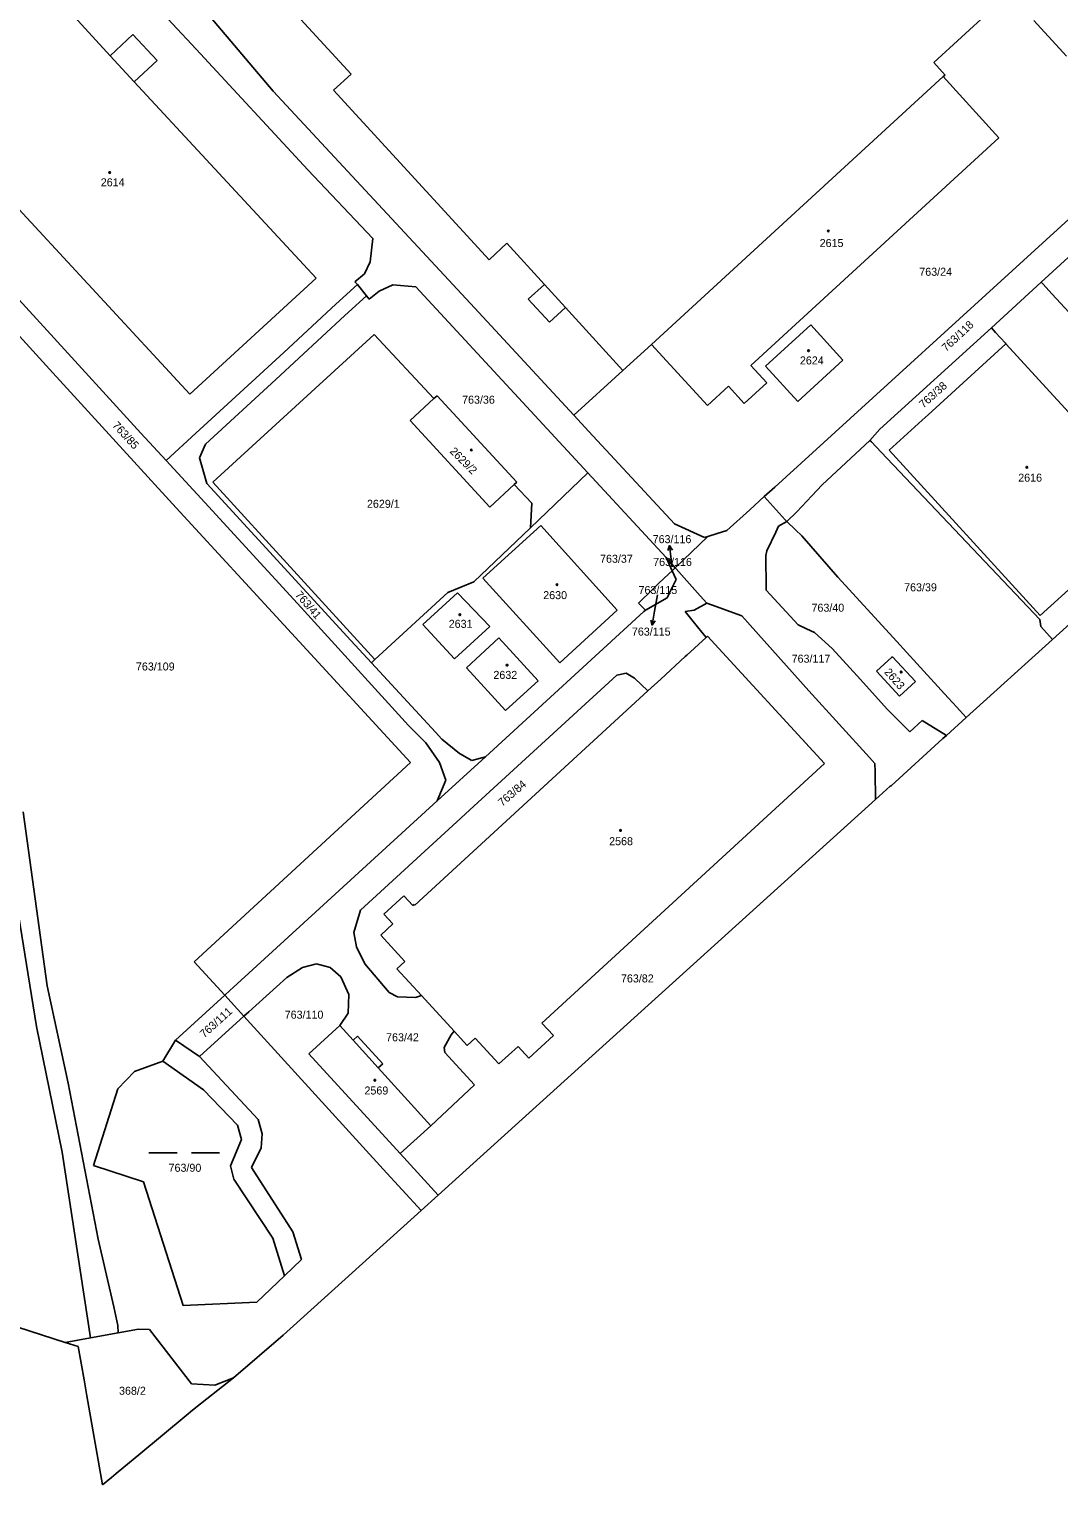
# Model space of a CAD drawing. Extents: x -735249 to -729401, y -1124843 to -1121828.
# Drawn here: x -733685.5 to -733466.8, y -1124842.6 to -1124533.4 of the extents above; entities that cross this region are included whole.
import ezdxf

# ---------------------------------------------------------------- set-up
doc = ezdxf.new("R2010")
doc.units = 0
for name, color, linetype in [('Vrstva 1', 7, 'Continuous'), ('Vrstva 13', 7, 'Continuous'), ('Vrstva 16', 7, 'Continuous'), ('Vrstva 18', 7, 'Continuous'), ('Vrstva 19', 7, 'Continuous'), ('Vrstva 25', 7, 'Continuous'), ('Vrstva 4', 7, 'Continuous')]:
    doc.layers.add(name, color=color, linetype=linetype)

msp = doc.modelspace()

# ---------------------------------------------------------------- linework, layer by layer
at = {"layer": 'Vrstva 1'}
for points in [[(-733684.28, -1124521.51), (-733668.29, -1124539.07)], [(-733617.15, -1124542.95), (-733636.87, -1124521.46)], [(-733660.09, -1124526.84), (-733650.07, -1124537.7)], [(-733633.7, -1124546.56), (-733647.02, -1124530.84)], [(-733481.62, -1124529.75), (-733493.36, -1124540.48)], [(-733472.16, -1124531.61), (-733465.23, -1124539.12)], [(-733668.29, -1124539.07), (-733663.46, -1124534.57)], [(-733663.46, -1124534.57), (-733658.34, -1124540.06)], [(-733658.34, -1124540.06), (-733663.18, -1124544.58)], [(-733650.07, -1124537.7), (-733626.34, -1124563.31)], [(-733493.36, -1124540.48), (-733490.98, -1124543.16)], [(-733617.15, -1124542.95), (-733620.86, -1124546.35)], [(-733491.39, -1124543.5), (-733553.34, -1124600.36)], [(-733490.98, -1124543.16), (-733491.39, -1124543.5)], [(-733479.6, -1124556.51), (-733491.39, -1124543.5)], [(-733651.42, -1124610.95), (-733711.16, -1124546.38)], [(-733624.55, -1124586.31), (-733663.18, -1124544.58)], [(-733591.78, -1124591.68), (-733633.7, -1124546.56)], [(-733620.86, -1124546.35), (-733587.79, -1124582.38)], [(-733532.23, -1124604.87), (-733479.6, -1124556.51)], [(-733470.57, -1124587.16), (-733459.91, -1124577.41), (-733457.7, -1124575.39), (-733442.33, -1124561.34)], [(-733626.34, -1124563.31), (-733612.53, -1124577.84)], [(-733458.57, -1124568.11), (-733461.75, -1124571.01), (-733463.97, -1124573.03), (-733527.19, -1124630.66)], [(-733655.04, -1124634.25), (-733680.48, -1124606.38), (-733705.37, -1124579.11)], [(-733613.09, -1124582.85), (-733612.53, -1124577.84)], [(-733587.79, -1124582.38), (-733584.09, -1124578.9)], [(-733584.09, -1124578.9), (-733576.09, -1124587.66)], [(-733694.59, -1124583.39), (-733681.69, -1124597.39)], [(-733614.28, -1124585.35), (-733613.09, -1124582.85)], [(-733651.42, -1124610.95), (-733624.55, -1124586.31)], [(-733616.33, -1124587.05), (-733614.28, -1124585.35)], [(-733616.33, -1124587.05), (-733615.8, -1124587.67)], [(-733615.8, -1124587.67), (-733620.35, -1124591.82)], [(-733618.45, -1124594.2), (-733613.89, -1124590.03)], [(-733615.8, -1124587.67), (-733613.89, -1124590.03)], [(-733613.89, -1124590.03), (-733613.27, -1124590.77)], [(-733611.21, -1124589.07), (-733613.27, -1124590.77)], [(-733608.28, -1124587.75), (-733611.21, -1124589.07)], [(-733603.37, -1124588.13), (-733608.28, -1124587.75)], [(-733580.75, -1124612.6), (-733603.37, -1124588.13)], [(-733576.09, -1124587.66), (-733579.51, -1124590.79)], [(-733481.14, -1124596.86), (-733470.57, -1124587.16)], [(-733470.57, -1124587.16), (-733470.26, -1124587.49), (-733468.23, -1124589.7), (-733457.62, -1124601.18)], [(-733631.44, -1124602.08), (-733620.35, -1124591.82)], [(-733591.78, -1124591.68), (-733569.83, -1124615.39)], [(-733579.51, -1124590.79), (-733575.02, -1124595.64)], [(-733575.02, -1124595.64), (-733571.63, -1124592.54)], [(-733571.63, -1124592.54), (-733559.42, -1124605.9)], [(-733618.45, -1124594.2), (-733633.14, -1124607.81)], [(-733519.53, -1124596.24), (-733529.12, -1124605.02)], [(-733512.71, -1124603.69), (-733519.53, -1124596.24)], [(-733681.69, -1124597.39), (-733661.76, -1124619.22)], [(-733646.49, -1124629.63), (-733612.26, -1124598.24)], [(-733612.26, -1124598.24), (-733599.54, -1124611.87)], [(-733504.86, -1124618.4), (-733481.14, -1124596.86)], [(-733481.14, -1124596.86), (-733480.26, -1124597.83), (-733478.17, -1124600.11), (-733478.07, -1124600.22)], [(-733650.09, -1124619.2), (-733631.44, -1124602.08)], [(-733559.42, -1124605.9), (-733553.34, -1124600.36)], [(-733553.34, -1124600.36), (-733541.48, -1124613.33)], [(-733478.07, -1124600.22), (-733486.33, -1124607.75)], [(-733478.07, -1124600.22), (-733445.95, -1124635.32)], [(-733528.87, -1124608.55), (-733532.23, -1124604.87)], [(-733529.12, -1124605.02), (-733522.3, -1124612.47)], [(-733522.3, -1124612.47), (-733512.71, -1124603.69)], [(-733633.14, -1124607.81), (-733648.04, -1124621.55)], [(-733569.83, -1124615.39), (-733559.42, -1124605.9)], [(-733533.66, -1124612.93), (-733528.87, -1124608.55)], [(-733486.33, -1124607.75), (-733494.62, -1124615.32)], [(-733598.89, -1124611.28), (-733599.54, -1124611.87)], [(-733581.96, -1124629.61), (-733598.89, -1124611.28)], [(-733541.48, -1124613.33), (-733537.02, -1124609.25)], [(-733537.02, -1124609.25), (-733533.66, -1124612.93)], [(-733599.54, -1124611.87), (-733604.62, -1124616.5)], [(-733566.85, -1124627.66), (-733580.75, -1124612.6)], [(-733604.62, -1124616.5), (-733587.71, -1124634.95)], [(-733569.83, -1124615.39), (-733566.63, -1124618.88)], [(-733494.62, -1124615.32), (-733495.85, -1124616.44), (-733502.89, -1124622.85)], [(-733661.76, -1124619.22), (-733656.39, -1124624.99)], [(-733656.39, -1124624.99), (-733650.09, -1124619.2)], [(-733566.63, -1124618.88), (-733548.48, -1124638.45)], [(-733517.08, -1124630.19), (-733506.95, -1124620.75)], [(-733506.95, -1124620.75), (-733504.86, -1124618.4)], [(-733506.95, -1124620.75), (-733506.63, -1124621.09), (-733504.57, -1124623.26), (-733470.9, -1124658.76)], [(-733648.04, -1124621.55), (-733649.32, -1124624.45)], [(-733502.89, -1124622.85), (-733470.79, -1124657.97)], [(-733656.39, -1124624.99), (-733648.21, -1124633.91)], [(-733649.32, -1124624.45), (-733647.78, -1124629.92)], [(-733647.78, -1124629.92), (-733617.2, -1124663.24)], [(-733646.49, -1124629.63), (-733612.08, -1124667.31)], [(-733587.71, -1124634.95), (-733582.51, -1124630.12)], [(-733582.51, -1124630.12), (-733581.96, -1124629.61)], [(-733582.51, -1124630.12), (-733578.78, -1124634.11)], [(-733579.04, -1124639.3), (-733566.85, -1124627.66)], [(-733566.85, -1124627.66), (-733550.26, -1124645.62)], [(-733524.61, -1124638), (-733522.46, -1124635.9), (-733519.3, -1124632.54), (-733517.08, -1124630.19)], [(-733537.35, -1124639.92), (-733532.47, -1124635.47), (-733529.41, -1124632.68)], [(-733529.41, -1124632.68), (-733527.19, -1124630.66)], [(-733529.41, -1124632.68), (-733524.93, -1124637.64), (-733524.61, -1124638)], [(-733655.04, -1124634.25), (-733604.5, -1124689.14)], [(-733627.73, -1124656.24), (-733648.21, -1124633.91)], [(-733578.78, -1124634.11), (-733579.04, -1124639.3)], [(-733591.09, -1124650.8), (-733579.04, -1124639.3)], [(-733589.14, -1124649.99), (-733576.87, -1124638.86)], [(-733576.87, -1124638.86), (-733560.62, -1124656.78)], [(-733548.48, -1124638.45), (-733542.06, -1124641.4)], [(-733526.36, -1124638.94), (-733526.95, -1124640.21), (-733528.82, -1124644.19)], [(-733524.61, -1124638), (-733526.36, -1124638.94)], [(-733521.4, -1124641.03), (-733522.78, -1124639.73), (-733524.61, -1124638)], [(-733541.4, -1124641.19), (-733548.31, -1124647.8)], [(-733542.06, -1124641.4), (-733541.4, -1124641.19)], [(-733541.4, -1124641.19), (-733539.37, -1124640.56), (-733537.35, -1124639.92)], [(-733513.8, -1124649.78), (-733521.4, -1124641.03)], [(-733550.26, -1124645.62), (-733548.97, -1124648.43)], [(-733548.31, -1124647.8), (-733550.26, -1124645.62)], [(-733528.82, -1124644.19), (-733529.08, -1124645.21)], [(-733529.08, -1124645.21), (-733529.08, -1124645.38), (-733529.03, -1124651.93), (-733529.02, -1124652.59)], [(-733548.97, -1124648.43), (-733549.66, -1124649.09), (-733551.83, -1124651.17), (-733552.05, -1124651.38)], [(-733548.31, -1124647.8), (-733548.74, -1124648.22), (-733548.97, -1124648.43)], [(-733548.97, -1124648.43), (-733548.1, -1124650.31)], [(-733541.57, -1124655.32), (-733542.98, -1124653.75), (-733548.13, -1124648), (-733548.31, -1124647.8)], [(-733596.58, -1124653.09), (-733591.09, -1124650.8)], [(-733572.79, -1124667.98), (-733589.14, -1124649.99)], [(-733548.1, -1124650.31), (-733549.57, -1124653.28), (-733549.83, -1124653.8), (-733550.04, -1124654.22), (-733554.64, -1124656.84)], [(-733552.05, -1124651.38), (-733553.04, -1124652.33)], [(-733501.26, -1124663.49), (-733513.8, -1124649.78)], [(-733462.52, -1124650.43), (-733470.79, -1124657.97)], [(-733612.08, -1124667.31), (-733596.58, -1124653.09)], [(-733601.9, -1124659.84), (-733594.55, -1124653.1)], [(-733594.55, -1124653.1), (-733587.7, -1124660.25)], [(-733553.04, -1124652.33), (-733556.13, -1124655.29)], [(-733522.17, -1124659.9), (-733529.02, -1124652.59)], [(-733604.97, -1124681.29), (-733627.73, -1124656.24)], [(-733588.62, -1124687.94), (-733554.94, -1124657.11)], [(-733560.62, -1124656.78), (-733572.79, -1124667.98)], [(-733556.13, -1124655.29), (-733554.64, -1124656.84)], [(-733554.94, -1124657.11), (-733554.64, -1124656.84)], [(-733544.26, -1124656.79), (-733546.17, -1124657.11)], [(-733546.17, -1124657.11), (-733544.47, -1124659.24), (-733541.77, -1124662.61)], [(-733541.57, -1124655.32), (-733544.26, -1124656.79)], [(-733534.18, -1124658), (-733540.62, -1124655.66), (-733541.57, -1124655.32)], [(-733519.93, -1124673.91), (-733534.18, -1124658)], [(-733595.21, -1124667.15), (-733601.9, -1124659.84)], [(-733587.7, -1124660.25), (-733595.21, -1124667.15)], [(-733518.75, -1124661.55), (-733520.4, -1124660.75), (-733522.17, -1124659.9)], [(-733470.9, -1124658.76), (-733470.64, -1124660.27)], [(-733470.64, -1124660.27), (-733468.2, -1124663.04)], [(-733617.2, -1124663.24), (-733612.83, -1124668)], [(-733592.65, -1124669.04), (-733585.79, -1124662.69)], [(-733585.79, -1124662.69), (-733577.43, -1124671.79)], [(-733546.18, -1124666.67), (-733545.86, -1124666.37), (-733541.77, -1124662.61)], [(-733541.44, -1124662.31), (-733541.77, -1124662.61)], [(-733516.59, -1124689.4), (-733541.44, -1124662.31)], [(-733514.98, -1124664.92), (-733518.75, -1124661.55)], [(-733490.34, -1124675.42), (-733499.23, -1124665.7), (-733501.26, -1124663.49)], [(-733612.83, -1124668), (-733612.08, -1124667.31)], [(-733546.18, -1124666.67), (-733551.39, -1124671.45)], [(-733508.97, -1124671.56), (-733514.98, -1124664.92)], [(-733502.2, -1124666.75), (-733502.28, -1124666.82), (-733505.56, -1124669.75)], [(-733497.31, -1124671.99), (-733502.2, -1124666.75)], [(-733612.83, -1124668), (-733599.2, -1124682.74)], [(-733584.33, -1124678.12), (-733592.65, -1124669.04)], [(-733558.74, -1124670.18), (-733560.38, -1124670.54), (-733560.71, -1124670.61)], [(-733556.99, -1124671.26), (-733558.74, -1124670.18)], [(-733505.56, -1124669.75), (-733500.69, -1124675.08)], [(-733560.71, -1124670.61), (-733591.09, -1124698.46), (-733594.72, -1124701.79), (-733615.12, -1124720.49)], [(-733577.43, -1124671.79), (-733584.33, -1124678.12)], [(-733554.13, -1124673.97), (-733556.9, -1124671.34), (-733556.99, -1124671.26)], [(-733551.39, -1124671.45), (-733554.13, -1124673.97)], [(-733503.31, -1124677.82), (-733508.97, -1124671.56)], [(-733500.69, -1124675.08), (-733497.31, -1124671.99)], [(-733603.64, -1124719.45), (-733554.13, -1124673.97)], [(-733505.9, -1124689.4), (-733507.06, -1124688.12), (-733519.93, -1124673.91)], [(-733486.52, -1124679.6), (-733487.19, -1124678.87), (-733487.92, -1124678.07), (-733488.54, -1124677.39), (-733490.34, -1124675.42)], [(-733503.31, -1124677.82), (-733499.67, -1124681.46), (-733498.49, -1124682.63)], [(-733604.97, -1124681.29), (-733601.28, -1124685.02)], [(-733597.89, -1124684.24), (-733599.2, -1124682.74)], [(-733495.87, -1124680.23), (-733498.49, -1124682.63)], [(-733490.73, -1124683.41), (-733495.87, -1124680.23)], [(-733601.28, -1124685.02), (-733598.38, -1124689.14)], [(-733594.09, -1124687.25), (-733597.89, -1124684.24)], [(-733598.83, -1124697.31), (-733588.62, -1124687.94)], [(-733591.53, -1124688.73), (-733594.09, -1124687.25)], [(-733588.62, -1124687.94), (-733591.53, -1124688.73)], [(-733604.5, -1124689.14), (-733650.45, -1124731.5)], [(-733598.38, -1124689.14), (-733597.03, -1124692.92)], [(-733576.61, -1124744.51), (-733516.59, -1124689.4)], [(-733505.9, -1124689.4), (-733505.88, -1124691.08), (-733505.81, -1124697.05)], [(-733597.03, -1124692.92), (-733598.83, -1124697.31)], [(-733643.98, -1124738.6), (-733642.88, -1124737.59), (-733641.34, -1124736.19), (-733598.83, -1124697.31)], [(-733681.65, -1124736.59), (-733686.75, -1124699.66)], [(-733689.21, -1124712.77), (-733683.92, -1124745.21)], [(-733610.19, -1124721.39), (-733605.95, -1124717.45)], [(-733605.95, -1124717.45), (-733604.03, -1124719.54)], [(-733604.03, -1124719.54), (-733603.78, -1124719.3)], [(-733603.78, -1124719.3), (-733603.64, -1124719.45)], [(-733615.12, -1124720.49), (-733616.54, -1124725.29)], [(-733608.3, -1124723.45), (-733610.19, -1124721.39)], [(-733616.54, -1124725.29), (-733616.02, -1124728.29)], [(-733610.85, -1124725.8), (-733608.3, -1124723.45)], [(-733605.71, -1124731.41), (-733610.85, -1124725.8)], [(-733616.02, -1124728.29), (-733614.24, -1124731.92)], [(-733650.45, -1124731.5), (-733643.98, -1124738.6)], [(-733627.45, -1124732.67), (-733624.5, -1124731.89)], [(-733624.5, -1124731.89), (-733621.59, -1124732.72)], [(-733614.24, -1124731.92), (-733609.06, -1124738.01)], [(-733607.41, -1124732.96), (-733605.71, -1124731.41)], [(-733639.91, -1124743.06), (-733638.85, -1124742.1), (-733637.38, -1124740.75), (-733630.82, -1124734.79)], [(-733630.82, -1124734.79), (-733627.45, -1124732.67)], [(-733621.59, -1124732.72), (-733619.34, -1124734.7)], [(-733619.34, -1124734.7), (-733617.62, -1124738.42)], [(-733602.2, -1124738.65), (-733607.41, -1124732.96)], [(-733681.65, -1124736.59), (-733677.19, -1124757.27)], [(-733617.62, -1124738.42), (-733617.76, -1124742.38)], [(-733609.06, -1124738.01), (-733607.26, -1124738.96)], [(-733654.41, -1124748.13), (-733643.98, -1124738.6)], [(-733643.98, -1124738.6), (-733639.91, -1124743.06)], [(-733607.26, -1124738.96), (-733603.46, -1124739.09)], [(-733603.46, -1124739.09), (-733602.2, -1124738.65)], [(-733595.23, -1124746.25), (-733602.2, -1124738.65)], [(-733639.91, -1124743.06), (-733649.33, -1124751.62)], [(-733610.3, -1124775.55), (-733639.91, -1124743.06)], [(-733617.76, -1124742.38), (-733619.52, -1124744.99)], [(-733576.61, -1124744.51), (-733574.17, -1124747.16)], [(-733678.49, -1124771.9), (-733683.92, -1124745.21)], [(-733619.52, -1124744.99), (-733626.1, -1124751)], [(-733616.7, -1124748.11), (-733619.52, -1124744.99)], [(-733615.77, -1124747.27), (-733616.7, -1124748.11)], [(-733610.43, -1124753.18), (-733615.77, -1124747.27)], [(-733595.88, -1124746.98), (-733597.38, -1124749.69)], [(-733595.23, -1124746.25), (-733595.88, -1124746.98)], [(-733592.49, -1124749.24), (-733595.23, -1124746.25)], [(-733590.79, -1124747.68), (-733592.49, -1124749.24)], [(-733585.75, -1124753.18), (-733590.79, -1124747.68)], [(-733574.17, -1124747.16), (-733579.39, -1124751.95)], [(-733654.41, -1124748.13), (-733657.13, -1124752.61)], [(-733649.33, -1124751.62), (-733654.41, -1124748.13)], [(-733597.38, -1124749.69), (-733597.26, -1124750.74)], [(-733597.26, -1124750.74), (-733590.92, -1124757.64)], [(-733581.69, -1124749.45), (-733585.75, -1124753.18)], [(-733579.39, -1124751.95), (-733581.69, -1124749.45)], [(-733657.13, -1124752.61), (-733663.14, -1124754.76)], [(-733636.89, -1124765.01), (-733649.33, -1124751.62)], [(-733626.1, -1124751), (-733606.7, -1124772.23)], [(-733611.36, -1124754.02), (-733610.43, -1124753.18)], [(-733600.2, -1124766.35), (-733611.36, -1124754.02)], [(-733663.14, -1124754.76), (-733666.7, -1124758.45)], [(-733677.19, -1124757.27), (-733670.87, -1124790.38)], [(-733666.7, -1124758.45), (-733671.82, -1124774.73)], [(-733590.92, -1124757.64), (-733600.2, -1124766.35)], [(-733636.05, -1124768.04), (-733636.89, -1124765.01)], [(-733606.7, -1124772.23), (-733600.2, -1124766.35)], [(-733636.25, -1124771.01), (-733636.05, -1124768.04)], [(-733678.49, -1124771.9), (-733672.46, -1124811.34)], [(-733638.29, -1124775.19), (-733636.25, -1124771.01)], [(-733606.7, -1124772.23), (-733598.65, -1124781.03)], [(-733671.82, -1124774.73), (-733661.25, -1124778.23)], [(-733629.49, -1124788.82), (-733638.29, -1124775.19)], [(-733602.29, -1124784.34), (-733610.3, -1124775.55)], [(-733661.25, -1124778.23), (-733652.79, -1124804.47)], [(-733670.87, -1124790.38), (-733667.49, -1124804.75)], [(-733627.69, -1124794.69), (-733629.49, -1124788.82)], [(-733631.3, -1124798.15), (-733627.69, -1124794.69)], [(-733637.14, -1124803.74), (-733631.3, -1124798.15)], [(-733667.49, -1124804.75), (-733666.7, -1124808.7)], [(-733652.79, -1124804.47), (-733637.14, -1124803.74)], [(-733666.7, -1124808.7), (-733666.64, -1124810.3)], [(-733666.64, -1124810.3), (-733662.32, -1124809.48)], [(-733662.32, -1124809.48), (-733659.93, -1124809.58)], [(-733659.93, -1124809.58), (-733651, -1124821.13)], [(-733677.85, -1124812.36), (-733672.46, -1124811.34)], [(-733672.46, -1124811.34), (-733666.64, -1124810.3)], [(-733651, -1124821.13), (-733646.09, -1124821.4)], [(-733646.09, -1124821.4), (-733642.09, -1124819.83)]]:
    msp.add_lwpolyline(points, dxfattribs=at)
at = {"layer": 'Vrstva 13'}
for points in [[(-733442.15, -1124639.48), (-733468.2, -1124663.04)], [(-733486.52, -1124679.6), (-733468.2, -1124663.04)], [(-733490.73, -1124683.41), (-733486.52, -1124679.6)], [(-733502.47, -1124694.11), (-733491.46, -1124684.07)], [(-733491.46, -1124684.07), (-733490.73, -1124683.41)], [(-733505.81, -1124697.05), (-733502.66, -1124694.2)], [(-733502.66, -1124694.2), (-733502.47, -1124694.11)], [(-733505.81, -1124697.05), (-733598.65, -1124781.03)], [(-733598.65, -1124781.03), (-733602.29, -1124784.34)], [(-733631.55, -1124810.79), (-733602.29, -1124784.34)], [(-733730.6, -1124795.3), (-733677.85, -1124812.36)], [(-733677.85, -1124812.36), (-733675.08, -1124813.18)], [(-733642.09, -1124819.83), (-733631.55, -1124810.79)], [(-733675.08, -1124813.18), (-733673.84, -1124820.24)], [(-733673.84, -1124820.24), (-733673.24, -1124823.66)], [(-733650.08, -1124826.13), (-733642.09, -1124819.83)], [(-733673.24, -1124823.66), (-733672.82, -1124826.08)], [(-733672.82, -1124826.08), (-733669.94, -1124842.58)], [(-733657.65, -1124832.41), (-733651.72, -1124827.49)], [(-733651.72, -1124827.49), (-733651.24, -1124827.09)], [(-733651.24, -1124827.09), (-733650.08, -1124826.13)], [(-733661.81, -1124835.85), (-733657.65, -1124832.41)], [(-733667.01, -1124840.16), (-733661.81, -1124835.85)], [(-733668.02, -1124840.99), (-733667.01, -1124840.16)], [(-733669.94, -1124842.58), (-733668.02, -1124840.99)]]:
    msp.add_lwpolyline(points, dxfattribs=at)
at = {"layer": 'Vrstva 16'}
for points in [[(-733548.96, -1124647.62), (-733549.14, -1124646.08)], [(-733552.07, -1124653.58), (-733552.68, -1124657.02)]]:
    msp.add_lwpolyline(points, dxfattribs=at)
at = {"layer": 'Vrstva 25'}
for points in [[(-733549.869, -1124644.152), (-733549.49, -1124643.101), (-733548.877, -1124644.036)], [(-733549.14, -1124646.08), (-733549.49, -1124643.101)], [(-733552.68, -1124657.02), (-733553.206, -1124659.973)], [(-733552.539, -1124659.076), (-733553.206, -1124659.973), (-733553.522, -1124658.901)], [(-733660.06, -1124772.06), (-733654.06, -1124772.06)], [(-733651.06, -1124772.06), (-733645.06, -1124772.06)]]:
    msp.add_lwpolyline(points, dxfattribs=at)
for centre, radius in [((-733668.42, -1124563.87), 0.175), ((-733515.8, -1124576.3), 0.175), ((-733520, -1124601.7), 0.175), ((-733591.6, -1124622.78), 0.175), ((-733473.63, -1124626.46), 0.175), ((-733573.43, -1124651.4), 0.175), ((-733594.04, -1124657.77), 0.175), ((-733584, -1124668.49), 0.175), ((-733500.32, -1124669.93), 0.174), ((-733559.93, -1124703.6), 0.175), ((-733612.1, -1124756.63), 0.175)]:
    msp.add_circle(centre, radius, dxfattribs=at)
at = {"layer": 'Vrstva 4'}
for points in [[(-733663.18, -1124544.58), (-733668.29, -1124539.07)], [(-733571.63, -1124592.54), (-733576.09, -1124587.66)], [(-733616.7, -1124748.11), (-733611.36, -1124754.02)], [(-733657.13, -1124752.61), (-733648.45, -1124758.65)], [(-733648.45, -1124758.65), (-733641.23, -1124766.21)], [(-733641.23, -1124766.21), (-733640.39, -1124769.24)], [(-733640.39, -1124769.24), (-733642.77, -1124774.8)], [(-733642.77, -1124774.8), (-733642.04, -1124777.67)], [(-733642.04, -1124777.67), (-733633.79, -1124790.16)], [(-733633.79, -1124790.16), (-733631.3, -1124798.15)]]:
    msp.add_lwpolyline(points, dxfattribs=at)

# ---------------------------------------------------------------- texts
at = {"layer": 'Vrstva 16'}
for s, p in [('763/116', (-733553.098, -1124642.58)), ('763/115', (-733557.508, -1124662.21))]:
    msp.add_text(s, height=1.7, dxfattribs=at).set_placement(p)
at = {"layer": 'Vrstva 18'}
for s, p in [('763/24', (-733496.48, -1124585.79)), ('763/36', (-733593.57, -1124612.96)), ('763/37', (-733564.27, -1124646.74)), ('763/116', (-733552.988, -1124647.42)), ('763/115', (-733556.098, -1124653.38)), ('763/39', (-733499.7, -1124652.8)), ('763/40', (-733519.37, -1124657.14)), ('763/117', (-733523.588, -1124667.96)), ('763/109', (-733662.83, -1124669.62)), ('763/82', (-733559.83, -1124735.87)), ('763/110', (-733631.24, -1124743.57)), ('763/42', (-733609.71, -1124748.37)), ('763/90', (-733655.9, -1124776.08)), ('368/2', (-733666.42, -1124823.44))]:
    msp.add_text(s, height=1.7, dxfattribs=at).set_placement(p)
for s, rotation, p in [('763/118', 43.20034, (-733490.773, -1124602.021)), ('763/38', 41.90033, (-733495.605, -1124614.028)), ('763/85', 312.40248, (-733667.958, -1124617.652)), ('763/41', 311.00247, (-733629.128, -1124653.629)), ('763/84', 40.80033, (-733585.03, -1124698.578)), ('763/111', 42.00033, (-733648.326, -1124747.748))]:
    msp.add_text(s, height=1.7, rotation=rotation, dxfattribs=at).set_placement(p)
at = {"layer": 'Vrstva 19'}
for s, p in [('2614', (-733670.3, -1124566.79)), ('2615', (-733517.64, -1124579.69)), ('2624', (-733521.83, -1124604.62)), ('2616', (-733475.47, -1124629.52)), ('2629/1', (-733613.77, -1124635.07)), ('2630', (-733576.34, -1124654.47)), ('2631', (-733596.41, -1124660.56)), ('2632', (-733586.92, -1124671.41)), ('2568', (-733562.34, -1124706.73)), ('2569', (-733614.3, -1124759.67))]:
    msp.add_text(s, height=1.7, dxfattribs=at).set_placement(p)
for s, rotation, p in [('2629/2', 315.00251, (-733596.328, -1124623.2)), ('2623', 311.40248, (-733504.028, -1124670.047))]:
    msp.add_text(s, height=1.7, rotation=rotation, dxfattribs=at).set_placement(p)

doc.saveas('drawing.dxf')
